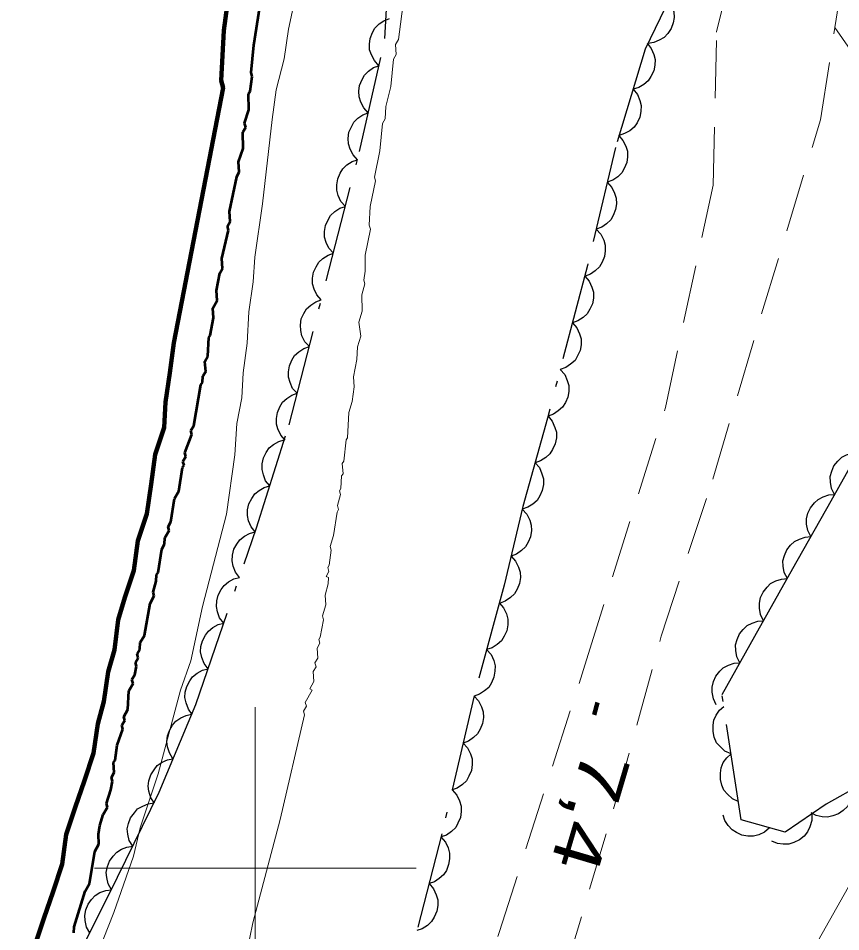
# Model space of a CAD drawing. Extents: x 355726 to 357533, y 5103782 to 5105258.
# Drawn here: x 355992.63 to 356018.2, y 5104698.03 to 5104726.42 of the extents above; entities that cross this region are included whole.
import ezdxf

# ---------------------------------------------------------------- set-up
doc = ezdxf.new("R2010")
doc.units = 0
doc.header["$LTSCALE"] = 0.6
for name, pattern in [('DASH_DOUBLE_DOT', [9.2, 5, -1.2, 0.3, -1.2, 0.3, -1.2]), ('DOT_DASHED', [7.7, 5, -1.2, 0.3, -1.2]), ('LONG_DASHED', [7.5, 6, -1.5]), ('MEDIUM_DASHED', [4.5, 3, -1.5])]:
    doc.linetypes.add(name, pattern=pattern)
for name, color, linetype, lineweight in [('1', 7, 'LONG_DASHED', 53), ('19', 7, 'Continuous', 13), ('2', 7, 'LONG_DASHED', 13), ('3', 7, 'Continuous', 140), ('4', 7, 'DASH_DOUBLE_DOT', 53), ('44', 7, 'Continuous', 25), ('61', 7, 'Continuous', 13)]:
    doc.layers.add(name, color=color, linetype=linetype, lineweight=lineweight)

msp = doc.modelspace()

# ---------------------------------------------------------------- linework, layer by layer
at = {"layer": '1'}
msp.add_lwpolyline([(355994.36, 5104697.99), (355994.37, 5104698.18), (355994.71, 5104699.29), (355994.84, 5104699.52), (355995.01, 5104700.52), (355995.14, 5104700.75), (355995.12, 5104701.06), (355995.17, 5104701.33), (355995.27, 5104701.67), (355995.4, 5104701.9), (355995.37, 5104702.01), (355995.51, 5104702.43), (355995.56, 5104702.7), (355995.53, 5104702.82), (355995.61, 5104702.97), (355995.59, 5104703.28), (355995.64, 5104703.36), (355995.7, 5104703.82), (355995.88, 5104704.32), (355995.85, 5104704.44), (355995.94, 5104704.59), (355995.91, 5104704.7), (355996.04, 5104704.93), (355996.07, 5104705.51), (355996.2, 5104705.74), (355996.16, 5104705.86), (355996.25, 5104706.01), (355996.31, 5104706.28), (355996.27, 5104706.39), (355996.36, 5104706.54), (355996.33, 5104706.66), (355996.41, 5104706.81), (355996.42, 5104707.01), (355996.55, 5104707.23), (355996.73, 5104708.23), (355996.86, 5104708.46), (355996.82, 5104708.58), (355996.92, 5104708.92), (355996.93, 5104709.12), (355996.98, 5104709.19), (355997.09, 5104709.92), (355997.18, 5104710.07), (355997.19, 5104710.27), (355997.32, 5104710.49), (355997.29, 5104710.61), (355997.37, 5104710.76), (355997.49, 5104711.49), (355997.62, 5104711.72), (355997.74, 5104712.45), (355997.79, 5104712.53), (355997.75, 5104712.64), (355997.84, 5104712.8), (355997.81, 5104712.91), (355998.03, 5104713.48), (355998, 5104713.6), (355998.09, 5104713.75), (355998.31, 5104715.02), (355998.36, 5104715.1), (355998.37, 5104715.29), (355998.46, 5104715.44), (355998.43, 5104715.75), (355998.52, 5104715.91), (355998.55, 5104716.49), (355998.6, 5104716.56), (355998.7, 5104717.1), (355998.68, 5104717.41), (355998.81, 5104717.64), (355998.79, 5104717.95), (355998.9, 5104718.49), (355998.98, 5104718.64), (355998.96, 5104718.95), (355999.17, 5104719.83), (355999.13, 5104719.95), (355999.22, 5104720.1), (355999.2, 5104720.41), (355999.42, 5104721.49), (355999.5, 5104721.64), (355999.48, 5104721.95), (355999.62, 5104722.37), (355999.61, 5104722.88), (355999.7, 5104723.03), (355999.66, 5104723.15), (355999.8, 5104723.57), (355999.79, 5104724.07), (355999.84, 5104724.15), (355999.9, 5104724.61), (355999.87, 5104724.73), (355999.95, 5104725.58), (356000.14, 5104726.77)], dxfattribs=at)
at = {"layer": '19', "linetype": 'MEDIUM_DASHED'}
for points in [[(355997.8, 5104670.73), (355999.08, 5104674.22), (356000.32, 5104676.94), (356001.43, 5104679.09), (356002.21, 5104680.3), (356006.1, 5104687.7), (356008.11, 5104691.5), (356009.62, 5104696.76), (356011.14, 5104701.84), (356012.62, 5104707.21), (356014.22, 5104712.09), (356015.74, 5104717.23), (356017.57, 5104723.26), (356018.4, 5104728.58), (356020.43, 5104734.04), (356022.51, 5104739.47), (356025.19, 5104744.96), (356027.66, 5104749.58), (356030.65, 5104755.01), (356033.08, 5104758.13), (356035.37, 5104761.13), (356036.71, 5104764.38), (356036.94, 5104767.51)], [(355997.24, 5104673.96), (355999.22, 5104678.15), (356000.21, 5104680.27), (356001.02, 5104681.7), (356001.91, 5104683.28), (356003.03, 5104685.63), (356005.07, 5104690.17), (356005.78, 5104692.77), (356007.59, 5104698.03), (356010.3, 5104706.48), (356012.75, 5104714.32), (356014.23, 5104721.23), (356014.34, 5104725.98), (356014.34, 5104725.99), (356015.02, 5104728.76), (356015.35, 5104729.87), (356016.02, 5104731.77), (356016.67, 5104733.29), (356018.02, 5104736.47)]]:
    msp.add_lwpolyline(points, dxfattribs=at)
at = {"layer": '2'}
for points in [[(355994.92, 5104696.91), (355995.6, 5104698.62), (355996.21, 5104700.37), (355996.42, 5104701.25), (355996.98, 5104702.93), (355997.67, 5104705.53), (355997.99, 5104706.44), (355998.36, 5104708.13), (355999.1, 5104711), (355999.36, 5104712.85), (355999.42, 5104713.82), (355999.58, 5104714.62), (355999.62, 5104715.4), (355999.75, 5104716.32), (355999.8, 5104717.29), (355999.93, 5104718.22), (355999.98, 5104718.99), (356000.22, 5104720.65), (356000.52, 5104723.27), (356000.65, 5104724.19), (356000.9, 5104725.15), (356001.03, 5104726.08), (356001.56, 5104728.57)], [(355999.6, 5104696.69), (355999.92, 5104698.3), (356000.77, 5104701.51), (356001.53, 5104704.77), (356001.5, 5104704.88), (356001.59, 5104705.04), (356001.55, 5104705.15), (356001.77, 5104705.53), (356001.69, 5104705.57), (356001.82, 5104705.8), (356001.8, 5104706.11), (356001.89, 5104706.26), (356001.85, 5104706.38), (356001.94, 5104706.53), (356001.92, 5104706.84), (356002.01, 5104706.99), (356001.97, 5104707.11), (356002.02, 5104707.18), (356002.12, 5104707.72), (356002.09, 5104707.84), (356002.19, 5104708.18), (356002.17, 5104708.49), (356002.26, 5104708.84), (356002.27, 5104709.03), (356002.2, 5104709.07), (356002.29, 5104709.22), (356002.25, 5104709.34), (356002.3, 5104709.42), (356002.36, 5104709.88), (356002.33, 5104710), (356002.43, 5104710.34), (356002.54, 5104711.07), (356002.59, 5104711.15), (356002.55, 5104711.27), (356002.65, 5104711.61), (356002.62, 5104711.73), (356002.66, 5104711.8), (356002.68, 5104712.19), (356002.73, 5104712.26), (356002.7, 5104712.58), (356002.75, 5104712.65), (356002.82, 5104713.31), (356002.87, 5104713.38), (356002.91, 5104714.16), (356003.01, 5104714.5), (356003.07, 5104714.96), (356003.05, 5104715.27), (356003.16, 5104715.81), (356003.18, 5104716.2), (356003.28, 5104716.54), (356003.22, 5104716.97), (356003.32, 5104717.31), (356003.31, 5104717.82), (356003.4, 5104718.16), (356003.37, 5104718.28), (356003.42, 5104718.55), (356003.41, 5104719.05), (356003.58, 5104719.86), (356003.54, 5104719.98), (356003.57, 5104720.56), (356003.74, 5104721.36), (356003.7, 5104721.48), (356003.87, 5104722.29), (356003.95, 5104723.14), (356004.04, 5104723.29), (356004.06, 5104723.67), (356004.21, 5104724.29), (356004.3, 5104725.14), (356004.38, 5104725.29), (356004.36, 5104725.6), (356004.45, 5104725.75), (356004.78, 5104728.25)]]:
    msp.add_lwpolyline(points, dxfattribs=at)
at = {"layer": '2', "linetype": 'Continuous'}
for points in [[(356021.79, 5104722.96), (356020.76, 5104723.51), (356019.58, 5104724.26), (356019.21, 5104724.53), (356018.9, 5104724.86), (356018.02, 5104726.13)], [(356003.45, 5104682.5), (356004.83, 5104682.12), (356008.94, 5104682.19), (356010.56, 5104682.07), (356011.96, 5104682.07), (356012.44, 5104682.4), (356012.9, 5104683.03), (356013.49, 5104684.09), (356013.86, 5104685.27), (356014.07, 5104686.54), (356014.1, 5104689.59), (356014.29, 5104690.98), (356014.74, 5104692.31), (356015.35, 5104693.75), (356015.99, 5104694.88), (356016.67, 5104696.28), (356019.26, 5104700.87)]]:
    msp.add_lwpolyline(points, dxfattribs=at)
at = {"layer": '3'}
msp.add_line((356010.64, 5104705.15), (356010.53, 5104704.77), dxfattribs=at)
at = {"layer": '4', "linetype": 'Continuous', "lineweight": 90}
msp.add_lwpolyline([(355999.15, 5104726.96), (355999.02, 5104726.03), (355998.98, 5104725.26), (355998.94, 5104724.48), (355999, 5104724.25), (355997.47, 5104716.33), (355997.34, 5104715.4), (355997.21, 5104714.48), (355997.17, 5104713.7), (355996.89, 5104712.86), (355996.76, 5104711.94), (355996.63, 5104711.01), (355996.35, 5104710.17), (355996.22, 5104709.25), (355995.94, 5104708.41), (355995.74, 5104707.72), (355995.62, 5104706.79), (355995.42, 5104706.1), (355995.29, 5104705.18), (355995.1, 5104704.49), (355994.97, 5104703.57), (355994.69, 5104702.73), (355994.4, 5104701.89), (355994.12, 5104701.05), (355993.99, 5104700.12), (355993.71, 5104699.28), (355993.43, 5104698.44), (355993.15, 5104697.6)], dxfattribs=at)
at = {"layer": '44', "linetype": 'DOT_DASHED'}
for points in [[(355992.63, 5104693.52), (355995.72, 5104699.72), (355997.01, 5104702.36), (355998.15, 5104705.09), (356000.04, 5104710.58), (356001.05, 5104713.78), (356003.24, 5104722.27), (356004.03, 5104725.79), (356004.5, 5104734.06)], [(356013.24, 5104727.79), (356012.12, 5104725.45), (356011.2, 5104722.4), (356010.33, 5104718.73), (356009.08, 5104713.99), (356008.32, 5104711.24), (356007.74, 5104708.8), (356006.8, 5104705.36), (356005.8, 5104701.07), (356004.95, 5104697.79)], [(356019.51, 5104702.98), (356017.75, 5104701.99), (356016.47, 5104701.12), (356015.1, 5104701.5), (356014.51, 5104705.4), (356015.53, 5104707.21), (356016.71, 5104709.31), (356017.9, 5104711.42), (356019.08, 5104713.53)]]:
    msp.add_lwpolyline(points, dxfattribs=at)
at = {"layer": '44'}
for points in [[(356012.86, 5104726.99), (356012.96, 5104726.81), (356013.01, 5104726.61), (356013.02, 5104726.44), (356012.99, 5104726.27), (356012.93, 5104726.1), (356012.82, 5104725.94), (356012.71, 5104725.82), (356012.56, 5104725.73), (356012.39, 5104725.66), (356012.21, 5104725.63)], [(356003.84, 5104724.94), (356003.7, 5104725.1), (356003.61, 5104725.28), (356003.55, 5104725.43), (356003.55, 5104725.61), (356003.57, 5104725.79), (356003.64, 5104725.97), (356003.72, 5104726.11), (356003.85, 5104726.24), (356004, 5104726.34), (356004.17, 5104726.41)], [(356012.18, 5104725.64), (356012.31, 5104725.48), (356012.39, 5104725.29), (356012.43, 5104725.13), (356012.42, 5104724.96), (356012.39, 5104724.78), (356012.3, 5104724.61), (356012.21, 5104724.47), (356012.08, 5104724.36), (356011.92, 5104724.26), (356011.75, 5104724.21)], [(356003.51, 5104723.48), (356003.37, 5104723.63), (356003.28, 5104723.81), (356003.23, 5104723.97), (356003.22, 5104724.15), (356003.24, 5104724.33), (356003.32, 5104724.51), (356003.39, 5104724.65), (356003.52, 5104724.77), (356003.67, 5104724.88), (356003.84, 5104724.94)], [(356011.75, 5104724.21), (356011.88, 5104724.05), (356011.95, 5104723.86), (356012, 5104723.7), (356011.99, 5104723.52), (356011.95, 5104723.34), (356011.87, 5104723.17), (356011.78, 5104723.03), (356011.64, 5104722.92), (356011.48, 5104722.83), (356011.31, 5104722.77)], [(356003.18, 5104722.02), (356003.04, 5104722.17), (356002.95, 5104722.35), (356002.9, 5104722.51), (356002.89, 5104722.68), (356002.91, 5104722.87), (356002.99, 5104723.04), (356003.06, 5104723.19), (356003.19, 5104723.31), (356003.34, 5104723.41), (356003.51, 5104723.48)], [(356011.29, 5104722.78), (356011.43, 5104722.62), (356011.52, 5104722.44), (356011.57, 5104722.28), (356011.57, 5104722.11), (356011.55, 5104721.93), (356011.47, 5104721.75), (356011.39, 5104721.61), (356011.27, 5104721.49), (356011.11, 5104721.38), (356010.94, 5104721.32)], [(356002.8, 5104720.57), (356002.66, 5104720.72), (356002.58, 5104720.91), (356002.53, 5104721.07), (356002.53, 5104721.24), (356002.56, 5104721.42), (356002.64, 5104721.6), (356002.72, 5104721.74), (356002.85, 5104721.86), (356003.01, 5104721.96), (356003.18, 5104722.02)], [(356010.94, 5104721.32), (356011.08, 5104721.16), (356011.17, 5104720.98), (356011.22, 5104720.82), (356011.23, 5104720.65), (356011.2, 5104720.47), (356011.13, 5104720.29), (356011.05, 5104720.15), (356010.92, 5104720.03), (356010.77, 5104719.92), (356010.6, 5104719.86)], [(356002.43, 5104719.11), (356002.29, 5104719.27), (356002.2, 5104719.45), (356002.15, 5104719.61), (356002.15, 5104719.79), (356002.18, 5104719.97), (356002.26, 5104720.15), (356002.34, 5104720.29), (356002.47, 5104720.41), (356002.63, 5104720.51), (356002.8, 5104720.57)], [(356010.6, 5104719.86), (356010.74, 5104719.71), (356010.83, 5104719.52), (356010.88, 5104719.36), (356010.88, 5104719.19), (356010.86, 5104719.01), (356010.78, 5104718.83), (356010.7, 5104718.69), (356010.57, 5104718.57), (356010.42, 5104718.46), (356010.25, 5104718.4)], [(356002.05, 5104717.66), (356001.91, 5104717.82), (356001.83, 5104718), (356001.78, 5104718.16), (356001.78, 5104718.34), (356001.81, 5104718.52), (356001.89, 5104718.69), (356001.97, 5104718.83), (356002.1, 5104718.95), (356002.26, 5104719.05), (356002.43, 5104719.11)], [(356010.24, 5104718.4), (356010.38, 5104718.24), (356010.46, 5104718.06), (356010.51, 5104717.9), (356010.51, 5104717.72), (356010.48, 5104717.54), (356010.4, 5104717.37), (356010.32, 5104717.23), (356010.19, 5104717.11), (356010.03, 5104717.01), (356009.86, 5104716.95)], [(356001.68, 5104716.21), (356001.54, 5104716.36), (356001.45, 5104716.55), (356001.41, 5104716.71), (356001.4, 5104716.88), (356001.43, 5104717.07), (356001.51, 5104717.24), (356001.59, 5104717.38), (356001.73, 5104717.5), (356001.88, 5104717.6), (356002.05, 5104717.66)], [(356009.86, 5104716.95), (356010, 5104716.79), (356010.08, 5104716.61), (356010.13, 5104716.45), (356010.13, 5104716.27), (356010.1, 5104716.09), (356010.02, 5104715.92), (356009.94, 5104715.78), (356009.8, 5104715.66), (356009.65, 5104715.56), (356009.48, 5104715.5)], [(356001.3, 5104714.76), (356001.16, 5104714.91), (356001.08, 5104715.1), (356001.03, 5104715.26), (356001.03, 5104715.43), (356001.06, 5104715.61), (356001.14, 5104715.79), (356001.22, 5104715.93), (356001.35, 5104716.05), (356001.51, 5104716.15), (356001.68, 5104716.21)], [(356009.48, 5104715.5), (356009.62, 5104715.34), (356009.7, 5104715.16), (356009.75, 5104715), (356009.75, 5104714.82), (356009.72, 5104714.64), (356009.64, 5104714.47), (356009.55, 5104714.33), (356009.42, 5104714.21), (356009.27, 5104714.11), (356009.1, 5104714.05)], [(356000.93, 5104713.3), (356000.79, 5104713.46), (356000.7, 5104713.65), (356000.66, 5104713.8), (356000.66, 5104713.98), (356000.69, 5104714.16), (356000.76, 5104714.34), (356000.85, 5104714.48), (356000.98, 5104714.6), (356001.13, 5104714.7), (356001.3, 5104714.76)], [(356009.1, 5104714.05), (356009.23, 5104713.89), (356009.31, 5104713.7), (356009.36, 5104713.55), (356009.36, 5104713.37), (356009.32, 5104713.19), (356009.24, 5104713.01), (356009.16, 5104712.88), (356009.03, 5104712.76), (356008.87, 5104712.66), (356008.7, 5104712.6)], [(356000.45, 5104711.88), (356000.32, 5104712.04), (356000.25, 5104712.23), (356000.21, 5104712.39), (356000.21, 5104712.57), (356000.25, 5104712.75), (356000.34, 5104712.92), (356000.43, 5104713.06), (356000.57, 5104713.17), (356000.73, 5104713.26), (356000.9, 5104713.31)], [(356018.01, 5104711.61), (356017.91, 5104711.8), (356017.88, 5104712), (356017.87, 5104712.17), (356017.92, 5104712.34), (356017.99, 5104712.5), (356018.11, 5104712.65), (356018.23, 5104712.77), (356018.38, 5104712.85), (356018.56, 5104712.91), (356018.74, 5104712.92)], [(356008.7, 5104712.6), (356008.83, 5104712.45), (356008.91, 5104712.26), (356008.96, 5104712.1), (356008.96, 5104711.92), (356008.92, 5104711.74), (356008.84, 5104711.57), (356008.76, 5104711.43), (356008.63, 5104711.31), (356008.47, 5104711.22), (356008.3, 5104711.16)], [(356000, 5104710.45), (355999.87, 5104710.61), (355999.79, 5104710.8), (355999.76, 5104710.96), (355999.76, 5104711.14), (355999.8, 5104711.32), (355999.89, 5104711.49), (355999.98, 5104711.63), (356000.12, 5104711.74), (356000.28, 5104711.83), (356000.45, 5104711.88)], [(356017.27, 5104710.31), (356017.18, 5104710.49), (356017.14, 5104710.69), (356017.14, 5104710.86), (356017.18, 5104711.03), (356017.26, 5104711.2), (356017.38, 5104711.35), (356017.5, 5104711.46), (356017.65, 5104711.54), (356017.83, 5104711.6), (356018.01, 5104711.61)], [(356008.3, 5104711.16), (356008.44, 5104711), (356008.53, 5104710.82), (356008.58, 5104710.66), (356008.59, 5104710.49), (356008.56, 5104710.3), (356008.48, 5104710.13), (356008.4, 5104709.99), (356008.28, 5104709.87), (356008.12, 5104709.76), (356007.95, 5104709.7)], [(355999.51, 5104709.03), (355999.38, 5104709.2), (355999.31, 5104709.39), (355999.28, 5104709.55), (355999.29, 5104709.73), (355999.33, 5104709.91), (355999.43, 5104710.07), (355999.52, 5104710.21), (355999.66, 5104710.32), (355999.82, 5104710.4), (356000, 5104710.45)], [(356016.54, 5104709), (356016.44, 5104709.19), (356016.41, 5104709.39), (356016.4, 5104709.55), (356016.45, 5104709.72), (356016.52, 5104709.89), (356016.64, 5104710.04), (356016.76, 5104710.15), (356016.92, 5104710.23), (356017.09, 5104710.29), (356017.27, 5104710.31)], [(356007.95, 5104709.7), (356008.09, 5104709.54), (356008.18, 5104709.36), (356008.23, 5104709.2), (356008.24, 5104709.03), (356008.21, 5104708.85), (356008.14, 5104708.67), (356008.06, 5104708.53), (356007.93, 5104708.41), (356007.77, 5104708.3), (356007.61, 5104708.24)], [(355999.02, 5104707.61), (355998.89, 5104707.78), (355998.82, 5104707.97), (355998.79, 5104708.13), (355998.8, 5104708.31), (355998.85, 5104708.49), (355998.94, 5104708.66), (355999.03, 5104708.79), (355999.17, 5104708.9), (355999.33, 5104708.99), (355999.51, 5104709.03)], [(356015.8, 5104707.69), (356015.71, 5104707.88), (356015.67, 5104708.08), (356015.67, 5104708.24), (356015.71, 5104708.41), (356015.79, 5104708.58), (356015.91, 5104708.73), (356016.02, 5104708.85), (356016.18, 5104708.93), (356016.36, 5104708.98), (356016.54, 5104709)], [(356007.59, 5104708.24), (356007.72, 5104708.09), (356007.81, 5104707.9), (356007.85, 5104707.74), (356007.85, 5104707.56), (356007.82, 5104707.38), (356007.74, 5104707.21), (356007.65, 5104707.07), (356007.52, 5104706.95), (356007.36, 5104706.85), (356007.19, 5104706.8)], [(356015.06, 5104706.38), (356014.97, 5104706.57), (356014.94, 5104706.77), (356014.93, 5104706.94), (356014.98, 5104707.11), (356015.05, 5104707.28), (356015.17, 5104707.42), (356015.29, 5104707.54), (356015.45, 5104707.62), (356015.62, 5104707.68), (356015.8, 5104707.69)], [(355998.53, 5104706.2), (355998.41, 5104706.36), (355998.34, 5104706.55), (355998.3, 5104706.72), (355998.31, 5104706.89), (355998.36, 5104707.07), (355998.45, 5104707.24), (355998.54, 5104707.37), (355998.68, 5104707.48), (355998.85, 5104707.57), (355999.02, 5104707.61)], [(356007.19, 5104706.8), (356007.33, 5104706.64), (356007.41, 5104706.45), (356007.46, 5104706.29), (356007.45, 5104706.12), (356007.42, 5104705.94), (356007.34, 5104705.76), (356007.26, 5104705.62), (356007.12, 5104705.51), (356006.97, 5104705.41), (356006.8, 5104705.35)], [(356014.33, 5104705.08), (356014.24, 5104705.26), (356014.2, 5104705.47), (356014.2, 5104705.63), (356014.24, 5104705.8), (356014.32, 5104705.97), (356014.44, 5104706.12), (356014.55, 5104706.23), (356014.71, 5104706.31), (356014.89, 5104706.37), (356015.06, 5104706.38)], [(355998.04, 5104704.78), (355997.92, 5104704.94), (355997.85, 5104705.14), (355997.81, 5104705.3), (355997.82, 5104705.47), (355997.87, 5104705.65), (355997.96, 5104705.82), (355998.05, 5104705.95), (355998.19, 5104706.06), (355998.36, 5104706.15), (355998.53, 5104706.2)], [(356006.8, 5104705.35), (356006.94, 5104705.2), (356007.03, 5104705.01), (356007.08, 5104704.86), (356007.09, 5104704.68), (356007.06, 5104704.5), (356006.99, 5104704.32), (356006.91, 5104704.18), (356006.78, 5104704.06), (356006.63, 5104703.95), (356006.46, 5104703.89)], [(356014.79, 5104703.55), (356014.6, 5104703.64), (356014.45, 5104703.78), (356014.34, 5104703.9), (356014.27, 5104704.07), (356014.23, 5104704.25), (356014.23, 5104704.44), (356014.25, 5104704.6), (356014.33, 5104704.76), (356014.43, 5104704.91), (356014.57, 5104705.03)], [(355997.44, 5104703.4), (355997.33, 5104703.58), (355997.27, 5104703.77), (355997.25, 5104703.93), (355997.27, 5104704.11), (355997.33, 5104704.28), (355997.43, 5104704.45), (355997.53, 5104704.57), (355997.68, 5104704.67), (355997.85, 5104704.75), (355998.02, 5104704.79)], [(356006.46, 5104703.89), (356006.6, 5104703.74), (356006.69, 5104703.55), (356006.74, 5104703.4), (356006.74, 5104703.22), (356006.72, 5104703.04), (356006.64, 5104702.86), (356006.57, 5104702.72), (356006.44, 5104702.6), (356006.28, 5104702.49), (356006.12, 5104702.43)], [(356015.01, 5104702.07), (356014.83, 5104702.16), (356014.68, 5104702.3), (356014.57, 5104702.42), (356014.5, 5104702.58), (356014.46, 5104702.76), (356014.46, 5104702.95), (356014.48, 5104703.12), (356014.55, 5104703.28), (356014.66, 5104703.43), (356014.79, 5104703.55)], [(355996.87, 5104702.02), (355996.75, 5104702.19), (355996.69, 5104702.39), (355996.67, 5104702.55), (355996.69, 5104702.72), (355996.75, 5104702.9), (355996.85, 5104703.06), (355996.95, 5104703.19), (355997.1, 5104703.29), (355997.27, 5104703.37), (355997.44, 5104703.4)], [(356006.12, 5104702.43), (356006.26, 5104702.27), (356006.35, 5104702.09), (356006.4, 5104701.93), (356006.4, 5104701.76), (356006.38, 5104701.58), (356006.3, 5104701.4), (356006.23, 5104701.26), (356006.1, 5104701.14), (356005.94, 5104701.03), (356005.78, 5104700.97)], [(356018.58, 5104702.46), (356018.57, 5104702.25), (356018.49, 5104702.06), (356018.41, 5104701.92), (356018.28, 5104701.79), (356018.13, 5104701.69), (356017.95, 5104701.63), (356017.79, 5104701.59), (356017.62, 5104701.6), (356017.44, 5104701.64), (356017.28, 5104701.72)], [(355996.19, 5104700.68), (355996.08, 5104700.86), (355996.04, 5104701.06), (355996.02, 5104701.22), (355996.06, 5104701.39), (355996.12, 5104701.57), (355996.24, 5104701.72), (355996.34, 5104701.84), (355996.5, 5104701.93), (355996.67, 5104702), (355996.85, 5104702.03)], [(356015.99, 5104701.25), (356015.83, 5104701.12), (356015.65, 5104701.04), (356015.49, 5104700.99), (356015.31, 5104700.99), (356015.13, 5104701.03), (356014.96, 5104701.11), (356014.82, 5104701.19), (356014.7, 5104701.33), (356014.6, 5104701.48), (356014.55, 5104701.65)], [(356017.3, 5104701.68), (356017.3, 5104701.48), (356017.24, 5104701.28), (356017.17, 5104701.13), (356017.06, 5104701), (356016.92, 5104700.88), (356016.74, 5104700.8), (356016.59, 5104700.75), (356016.41, 5104700.75), (356016.23, 5104700.77), (356016.06, 5104700.84)], [(356005.77, 5104700.97), (356005.91, 5104700.81), (356006, 5104700.63), (356006.04, 5104700.47), (356006.04, 5104700.29), (356006.01, 5104700.11), (356005.94, 5104699.93), (356005.85, 5104699.79), (356005.72, 5104699.68), (356005.57, 5104699.58), (356005.4, 5104699.52)], [(355995.53, 5104699.33), (355995.43, 5104699.51), (355995.38, 5104699.71), (355995.36, 5104699.87), (355995.4, 5104700.05), (355995.47, 5104700.22), (355995.58, 5104700.37), (355995.69, 5104700.5), (355995.84, 5104700.59), (355996.01, 5104700.65), (355996.19, 5104700.68)], [(356005.4, 5104699.52), (356005.54, 5104699.36), (356005.62, 5104699.17), (356005.67, 5104699.02), (356005.67, 5104698.84), (356005.64, 5104698.66), (356005.56, 5104698.48), (356005.48, 5104698.34), (356005.35, 5104698.22), (356005.19, 5104698.12), (356005.02, 5104698.06)], [(355994.86, 5104697.99), (355994.75, 5104698.17), (355994.71, 5104698.37), (355994.7, 5104698.53), (355994.73, 5104698.71), (355994.8, 5104698.88), (355994.91, 5104699.03), (355995.02, 5104699.15), (355995.17, 5104699.24), (355995.35, 5104699.31), (355995.53, 5104699.33)]]:
    msp.add_lwpolyline(points, dxfattribs=at)
at = {"layer": '61'}
for p, q in [((356000, 5104695), (356000, 5104705)), ((355995, 5104700), (356005, 5104700))]:
    msp.add_line(p, q, dxfattribs=at)

# ---------------------------------------------------------------- texts
at = {"layer": '3', "width": 1.35}
msp.add_text('7,4    ', height=1.5, rotation=253.491, dxfattribs=at).set_placement((356010.24, 5104703.78))

doc.saveas('drawing.dxf')
